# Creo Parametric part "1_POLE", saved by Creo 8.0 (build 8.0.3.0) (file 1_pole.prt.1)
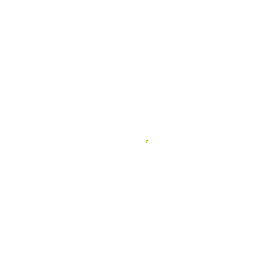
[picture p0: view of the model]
Units: millimeter Newton Second (mmNs); MM, TONNE, SECS

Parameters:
  PLACEMENT = "A"

Other parameters: MAJOR_DIAMETER, THREADS_PER_INCH, METRIC

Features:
  1. datum plane "DTM1"
  2. datum plane "DTM2"
  3. datum plane "DTM3"
  4. coordinate system
  5. datum plane "DTM4"
  6. datum plane "DTM5"
  7. protrusion
  8. chamfer

Other named items: CS0

Layers: 0_ALL_AXIS, 0_ALL_CSYS, 0_ALL_CURVES, 0_ALL_PLANES, 0_ALL_POINTS, 0_ALL_SURFS, POLE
